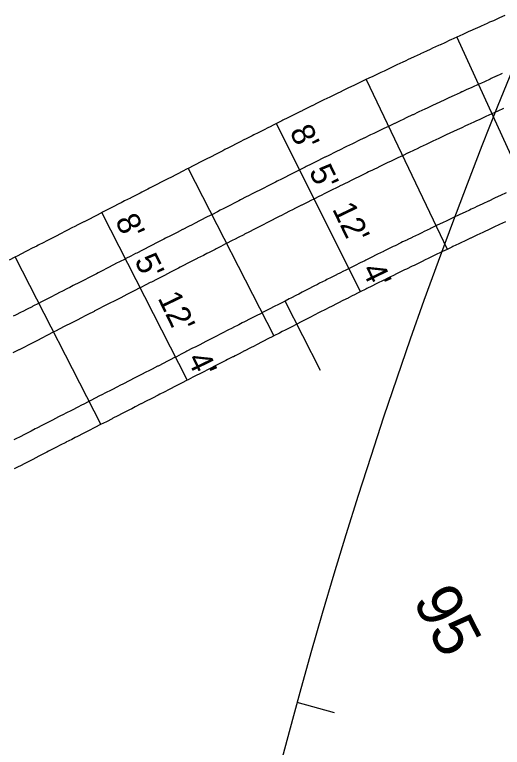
# Model space of a CAD drawing. Extents: x 2145147 to 2158018, y 137519 to 148068.
# Drawn here: x 2150223.5 to 2150298.8, y 143408.6 to 143521.5 of the extents above; entities that cross this region are included whole.
import ezdxf

# ---------------------------------------------------------------- set-up
doc = ezdxf.new("R2010")
doc.units = 0
for name, color, linetype in [('PR_Align_Ramp_A', 7, 'Continuous'), ('PR_Align_Ramp_A_Sta', 7, 'Continuous'), ('PR_Align_Ramp_B', 7, 'Continuous'), ('PR_Dimensions', 7, 'Continuous'), ('PR_Joint_Contraction', 7, 'Continuous'), ('PR_Joint_Long', 7, 'Continuous'), ('PR_Road_Concrete', 7, 'Continuous')]:
    doc.layers.add(name, color=color, linetype=linetype)

msp = doc.modelspace()

# ---------------------------------------------------------------- linework, layer by layer
at = {"layer": 'PR_Align_Ramp_A'}
msp.add_lwpolyline([(2150270.71, 143466.66), (2150265.25, 143477.35)], dxfattribs=at)
at = {"layer": 'PR_Align_Ramp_B'}
msp.add_lwpolyline([(2150272.91, 143413.89), (2150267.13, 143415.47)], dxfattribs=at)
msp.add_arc((2151085.75, 143191.05), 848.83, 152.5051, 261.84091, dxfattribs=at)
at = {"layer": 'PR_Joint_Contraction'}
for p, q in [((2150291.78, 143518.03), (2150303.8, 143491.64)), ((2150277.77, 143511.49), (2150290.27, 143485.32)), ((2150263.88, 143504.69), (2150276.87, 143478.76)), ((2150250.32, 143497.79), (2150263.53, 143471.97)), ((2150236.97, 143490.96), (2150250.18, 143465.14)), ((2150223.61, 143484.13), (2150236.82, 143458.31))]:
    msp.add_line(p, q, dxfattribs=at)
at = {"layer": 'PR_Joint_Long'}
for points in [[(2150298.76, 143512.41), (2150298.56, 143512.32), (2150297.89, 143512.01), (2150297.84, 143511.99), (2150297.06, 143511.64), (2150296.92, 143511.57), (2150296, 143511.16), (2150295.55, 143510.95), (2150295.07, 143510.73), (2150294.16, 143510.32), (2150294.05, 143510.27), (2150293.21, 143509.88), (2150292.58, 143509.6), (2150292.53, 143509.57), (2150292.28, 143509.46), (2150291.35, 143509.03), (2150291, 143508.86), (2150290.43, 143508.61), (2150289.82, 143508.32), (2150289.79, 143508.31), (2150288.58, 143507.74), (2150287.98, 143507.47), (2150287.67, 143507.32), (2150287.27, 143507.13), (2150286.74, 143506.88), (2150286.48, 143506.76), (2150285.8, 143506.44), (2150285.01, 143506.07), (2150284.92, 143506.03), (2150283.96, 143505.57), (2150283.48, 143505.34), (2150283.04, 143505.14), (2150282.18, 143504.73), (2150282.16, 143504.72), (2150281.19, 143504.25), (2150280.49, 143503.92), (2150280.3, 143503.83), (2150279.35, 143503.37), (2150278.96, 143503.18), (2150278.44, 143502.94), (2150277.48, 143502.47), (2150277.42, 143502.44), (2150276.65, 143502.07), (2150276.54, 143502.02), (2150275.97, 143501.74), (2150275.68, 143501.59), (2150274.75, 143501.15), (2150274.45, 143501), (2150273.85, 143500.7), (2150273.07, 143500.32), (2150273.01, 143500.29), (2150272.01, 143499.8), (2150271.45, 143499.52), (2150271.4, 143499.5), (2150271.1, 143499.35), (2150270.19, 143498.9), (2150269.99, 143498.8), (2150269.27, 143498.44), (2150268.5, 143498.06), (2150268.35, 143497.98), (2150267.45, 143497.53), (2150267.01, 143497.31), (2150266.53, 143497.07), (2150266.19, 143496.9), (2150265.6, 143496.61), (2150265.52, 143496.56), (2150264.71, 143496.15), (2150264.04, 143495.81), (2150263.8, 143495.69), (2150262.88, 143495.23), (2150262.54, 143495.06), (2150261.98, 143494.77), (2150260.2, 143493.86), (2150260.2, 143493.86), (2150260.17, 143493.85), (2150259.61, 143493.56), (2150259.28, 143493.39), (2150258.37, 143492.93), (2150258.14, 143492.81), (2150257.51, 143492.48), (2150256.73, 143492.08), (2150256.62, 143492.03), (2150255.72, 143491.57), (2150255.27, 143491.33), (2150254.83, 143491.11), (2150253.94, 143490.66), (2150253.81, 143490.59), (2150253.05, 143490.2), (2150252.36, 143489.85), (2150252.17, 143489.75), (2150251.28, 143489.29), (2150250.91, 143489.1), (2150250.38, 143488.83), (2150249.48, 143488.38), (2150249.44, 143488.35), (2150248.6, 143487.92), (2150248, 143487.62), (2150247.68, 143487.45), (2150247.6, 143487.41), (2150246.82, 143487.02), (2150246.54, 143486.87), (2150245.93, 143486.56), (2150245.12, 143486.14), (2150245.05, 143486.11), (2150244.15, 143485.65), (2150243.66, 143485.4), (2150243.26, 143485.19), (2150242.37, 143484.73), (2150242.2, 143484.65), (2150241.48, 143484.28), (2150240.72, 143483.89), (2150240.57, 143483.81), (2150239.7, 143483.37), (2150239.28, 143483.16), (2150238.81, 143482.91), (2150237.91, 143482.46), (2150237.83, 143482.41), (2150237.02, 143482), (2150236.41, 143481.69), (2150236.15, 143481.56), (2150235.25, 143481.1), (2150234.95, 143480.94), (2150234.36, 143480.64), (2150233.56, 143480.23), (2150233.54, 143480.22), (2150232.57, 143479.72), (2150232.04, 143479.45), (2150231.69, 143479.27), (2150230.81, 143478.82), (2150230.59, 143478.71), (2150229.9, 143478.36), (2150229.12, 143477.96), (2150229.01, 143477.9), (2150228.12, 143477.45), (2150227.67, 143477.22), (2150227.23, 143476.99), (2150226.34, 143476.54), (2150226.22, 143476.47), (2150225.46, 143476.08), (2150224.78, 143475.74), (2150224.56, 143475.62), (2150223.68, 143475.17), (2150223.33, 143475)], [(2150298.98, 143507.02), (2150298.07, 143506.61), (2150297.62, 143506.4), (2150297.14, 143506.18), (2150296.23, 143505.77), (2150296.12, 143505.72), (2150295.29, 143505.34), (2150294.67, 143505.05), (2150294.61, 143505.03), (2150294.37, 143504.92), (2150293.45, 143504.49), (2150293.1, 143504.33), (2150292.53, 143504.07), (2150291.83, 143503.74), (2150291.81, 143503.73), (2150290.69, 143503.21), (2150290.1, 143502.94), (2150289.78, 143502.79), (2150289.39, 143502.6), (2150288.86, 143502.35), (2150288.61, 143502.24), (2150287.93, 143501.92), (2150287.14, 143501.54), (2150287.04, 143501.5), (2150286.1, 143501.06), (2150285.62, 143500.83), (2150285.18, 143500.62), (2150284.28, 143500.19), (2150284.25, 143500.18), (2150283.35, 143499.74), (2150282.64, 143499.41), (2150282.45, 143499.32), (2150281.52, 143498.87), (2150281.13, 143498.68), (2150280.61, 143498.43), (2150279.67, 143497.98), (2150279.61, 143497.95), (2150278.84, 143497.58), (2150278.74, 143497.53), (2150278.15, 143497.24), (2150277.87, 143497.1), (2150276.95, 143496.65), (2150276.65, 143496.51), (2150276.05, 143496.21), (2150275.24, 143495.82), (2150275.19, 143495.79), (2150274.22, 143495.32), (2150273.67, 143495.04), (2150273.63, 143495.02), (2150273.31, 143494.87), (2150272.41, 143494.42), (2150272.21, 143494.32), (2150271.49, 143493.96), (2150270.73, 143493.58), (2150270.58, 143493.51), (2150269.68, 143493.06), (2150269.25, 143492.84), (2150268.77, 143492.6), (2150268.44, 143492.43), (2150267.86, 143492.14), (2150267.77, 143492.1), (2150266.96, 143491.69), (2150266.29, 143491.35), (2150266.06, 143491.23), (2150265.15, 143490.77), (2150264.81, 143490.6), (2150264.25, 143490.31), (2150262.73, 143489.54), (2150262.73, 143489.54), (2150262.45, 143489.4), (2150261.89, 143489.11), (2150261.56, 143488.94), (2150260.66, 143488.48), (2150260.43, 143488.36), (2150259.79, 143488.03), (2150259, 143487.63), (2150258.89, 143487.57), (2150258, 143487.12), (2150257.54, 143486.88), (2150257.11, 143486.66), (2150256.22, 143486.21), (2150256.09, 143486.14), (2150255.33, 143485.75), (2150254.64, 143485.4), (2150254.45, 143485.3), (2150253.55, 143484.84), (2150253.18, 143484.65), (2150252.66, 143484.38), (2150251.76, 143483.93), (2150251.72, 143483.9), (2150250.88, 143483.47), (2150250.28, 143483.17), (2150249.96, 143483.01), (2150249.88, 143482.96), (2150249.1, 143482.56), (2150248.82, 143482.42), (2150248.21, 143482.11), (2150247.39, 143481.69), (2150247.33, 143481.66), (2150246.43, 143481.2), (2150245.93, 143480.94), (2150245.54, 143480.74), (2150244.64, 143480.28), (2150244.47, 143480.2), (2150243.76, 143479.83), (2150243, 143479.44), (2150242.85, 143479.37), (2150241.98, 143478.92), (2150241.56, 143478.71), (2150241.08, 143478.46), (2150240.19, 143478.01), (2150240.11, 143477.96), (2150239.3, 143477.55), (2150238.68, 143477.23), (2150238.43, 143477.1), (2150237.53, 143476.64), (2150237.22, 143476.49), (2150236.63, 143476.19), (2150235.81, 143475.77), (2150235.79, 143475.76), (2150234.85, 143475.27), (2150234.32, 143475), (2150233.97, 143474.82), (2150233.08, 143474.37), (2150232.87, 143474.26), (2150232.18, 143473.91), (2150231.4, 143473.51), (2150231.29, 143473.45), (2150230.4, 143473), (2150229.95, 143472.77), (2150229.51, 143472.54), (2150228.62, 143472.09), (2150228.5, 143472.02), (2150227.73, 143471.63), (2150227.05, 143471.28), (2150226.84, 143471.17), (2150225.96, 143470.72), (2150225.61, 143470.54), (2150225.06, 143470.26), (2150224.22, 143469.83), (2150224.2, 143469.82), (2150223.28, 143469.35)], [(2150299.39, 143494.02), (2150298.48, 143493.6), (2150298.14, 143493.44), (2150297.57, 143493.18), (2150296.67, 143492.76), (2150296.66, 143492.75), (2150295.76, 143492.33), (2150295.18, 143492.06), (2150294.85, 143491.91), (2150294.47, 143491.73), (2150293.95, 143491.49), (2150293.7, 143491.37), (2150293.04, 143491.06), (2150292.23, 143490.68), (2150292.14, 143490.64), (2150291.24, 143490.21), (2150290.75, 143489.98), (2150290.33, 143489.78), (2150289.43, 143489.35), (2150289.29, 143489.28), (2150289.28, 143489.28), (2150288.53, 143488.92), (2150287.81, 143488.58), (2150287.62, 143488.49), (2150286.72, 143488.06), (2150286.34, 143487.87), (2150285.82, 143487.62), (2150284.92, 143487.19), (2150284.87, 143487.16), (2150284.12, 143486.8), (2150284.02, 143486.75), (2150283.4, 143486.45), (2150283.12, 143486.31), (2150282.22, 143485.88), (2150281.94, 143485.73), (2150281.33, 143485.43), (2150280.47, 143485.02), (2150280.43, 143484.99), (2150279.53, 143484.55), (2150279.01, 143484.3), (2150278.97, 143484.27), (2150278.63, 143484.11), (2150277.74, 143483.67), (2150277.55, 143483.57), (2150276.84, 143483.22), (2150276.09, 143482.85), (2150275.95, 143482.77), (2150275.05, 143482.33), (2150274.63, 143482.12), (2150274.16, 143481.88), (2150273.83, 143481.72), (2150273.27, 143481.43), (2150273.17, 143481.38), (2150272.37, 143480.98), (2150271.72, 143480.65), (2150271.48, 143480.53), (2150270.59, 143480.08), (2150270.26, 143479.91), (2150269.7, 143479.62), (2150268.81, 143479.17), (2150268.81, 143479.17), (2150268.72, 143479.12), (2150268.72, 143479.12), (2150267.92, 143478.71), (2150267.36, 143478.43), (2150267.03, 143478.26), (2150266.14, 143477.8), (2150265.91, 143477.68), (2150265.25, 143477.35), (2150264.46, 143476.94), (2150264.36, 143476.89), (2150263.47, 143476.43), (2150263, 143476.2), (2150262.58, 143475.98), (2150261.69, 143475.52), (2150261.55, 143475.45), (2150260.79, 143475.07), (2150260.1, 143474.71), (2150259.9, 143474.61), (2150259.01, 143474.16), (2150258.65, 143473.97), (2150258.12, 143473.7), (2150257.23, 143473.25), (2150257.2, 143473.23), (2150256.34, 143472.79), (2150255.74, 143472.48), (2150255.45, 143472.33), (2150255.37, 143472.29), (2150254.56, 143471.88), (2150254.29, 143471.74), (2150253.67, 143471.42), (2150252.84, 143471), (2150252.78, 143470.97), (2150251.89, 143470.51), (2150251.39, 143470.26), (2150251, 143470.06), (2150250.11, 143469.6), (2150249.94, 143469.51), (2150249.22, 143469.15), (2150248.49, 143468.77), (2150248.33, 143468.69), (2150247.44, 143468.24), (2150247.03, 143468.03), (2150246.55, 143467.78), (2150245.66, 143467.32), (2150245.58, 143467.29), (2150244.77, 143466.87), (2150244.13, 143466.54), (2150243.88, 143466.41), (2150242.99, 143465.96), (2150242.68, 143465.8), (2150242.1, 143465.5), (2150241.23, 143465.06), (2150241.21, 143465.05), (2150240.32, 143464.59), (2150239.78, 143464.31), (2150239.43, 143464.14), (2150238.54, 143463.68), (2150238.32, 143463.57), (2150237.65, 143463.23), (2150236.87, 143462.83), (2150236.76, 143462.77), (2150235.87, 143462.32), (2150235.42, 143462.09), (2150234.98, 143461.86), (2150234.09, 143461.4), (2150233.97, 143461.34), (2150233.2, 143460.95), (2150232.52, 143460.6), (2150232.31, 143460.49), (2150231.42, 143460.04), (2150231.07, 143459.86), (2150230.53, 143459.58), (2150229.64, 143459.13), (2150229.61, 143459.11), (2150228.75, 143458.67), (2150228.16, 143458.37), (2150227.86, 143458.22), (2150226.97, 143457.76), (2150226.71, 143457.63), (2150226.07, 143457.3), (2150225.26, 143456.89), (2150225.19, 143456.85), (2150224.29, 143456.39), (2150223.81, 143456.14), (2150223.4, 143455.94)]]:
    msp.add_lwpolyline(points, dxfattribs=at)
at = {"layer": 'PR_Road_Concrete'}
for points in [[(2150299.18, 143521.35), (2150298.36, 143520.99), (2150298.33, 143520.98), (2150297.39, 143520.56), (2150296.82, 143520.31), (2150296.45, 143520.14), (2150295.51, 143519.71), (2150295.29, 143519.62), (2150294.61, 143519.31), (2150294.57, 143519.29), (2150293.76, 143518.93), (2150293.63, 143518.87), (2150292.69, 143518.44), (2150292.23, 143518.23), (2150291.75, 143518.02), (2150290.81, 143517.59), (2150290.7, 143517.54), (2150289.88, 143517.16), (2150289.23, 143516.86), (2150289.17, 143516.83), (2150288.94, 143516.73), (2150288, 143516.3), (2150287.65, 143516.13), (2150287.07, 143515.86), (2150286.13, 143515.43), (2150286.12, 143515.42), (2150285.2, 143514.99), (2150284.6, 143514.71), (2150284.27, 143514.56), (2150283.87, 143514.38), (2150283.33, 143514.12), (2150283.08, 143514), (2150282.4, 143513.68), (2150281.56, 143513.29), (2150281.47, 143513.24), (2150280.54, 143512.8), (2150280.04, 143512.57), (2150279.6, 143512.36), (2150278.67, 143511.92), (2150278.53, 143511.85), (2150278.52, 143511.85), (2150277.74, 143511.48), (2150277, 143511.12), (2150276.81, 143511.03), (2150275.89, 143510.58), (2150275.49, 143510.39), (2150274.96, 143510.14), (2150274.03, 143509.69), (2150273.98, 143509.66), (2150273.2, 143509.29), (2150273.1, 143509.24), (2150272.46, 143508.93), (2150272.18, 143508.79), (2150271.25, 143508.34), (2150270.95, 143508.19), (2150270.32, 143507.88), (2150269.44, 143507.45), (2150269.4, 143507.43), (2150268.47, 143506.97), (2150267.94, 143506.71), (2150267.9, 143506.69), (2150267.55, 143506.52), (2150266.63, 143506.06), (2150266.43, 143505.96), (2150265.7, 143505.6), (2150264.93, 143505.21), (2150264.78, 143505.14), (2150263.86, 143504.68), (2150263.42, 143504.46), (2150262.94, 143504.22), (2150262.6, 143504.05), (2150262.02, 143503.76), (2150261.92, 143503.71), (2150261.1, 143503.29), (2150260.42, 143502.95), (2150260.18, 143502.83), (2150259.26, 143502.36), (2150258.92, 143502.19), (2150258.34, 143501.89), (2150257.43, 143501.43), (2150257.42, 143501.42), (2150257.33, 143501.38), (2150257.33, 143501.38), (2150256.53, 143500.97), (2150255.97, 143500.68), (2150255.64, 143500.51), (2150254.75, 143500.06), (2150254.52, 143499.94), (2150253.86, 143499.6), (2150253.07, 143499.2), (2150252.97, 143499.15), (2150252.08, 143498.69), (2150251.62, 143498.45), (2150251.19, 143498.23), (2150250.3, 143497.78), (2150250.17, 143497.71), (2150249.41, 143497.32), (2150248.71, 143496.97), (2150248.52, 143496.87), (2150247.63, 143496.41), (2150247.26, 143496.23), (2150246.74, 143495.96), (2150245.85, 143495.5), (2150245.81, 143495.48), (2150244.96, 143495.05), (2150244.36, 143494.74), (2150244.07, 143494.59), (2150243.98, 143494.55), (2150243.18, 143494.14), (2150242.91, 143494), (2150242.29, 143493.68), (2150241.46, 143493.26), (2150241.4, 143493.22), (2150240.51, 143492.77), (2150240, 143492.51), (2150239.62, 143492.31), (2150238.73, 143491.86), (2150238.55, 143491.77), (2150237.83, 143491.4), (2150237.1, 143491.03), (2150236.94, 143490.95), (2150236.05, 143490.49), (2150235.65, 143490.28), (2150235.17, 143490.04), (2150234.27, 143489.58), (2150234.2, 143489.54), (2150233.38, 143489.13), (2150232.74, 143488.8), (2150232.49, 143488.67), (2150231.6, 143488.21), (2150231.29, 143488.06), (2150230.71, 143487.76), (2150229.84, 143487.31), (2150229.82, 143487.3), (2150228.93, 143486.85), (2150228.39, 143486.57), (2150228.04, 143486.39), (2150227.15, 143485.94), (2150226.94, 143485.83), (2150226.26, 143485.48), (2150225.49, 143485.08), (2150225.37, 143485.03), (2150224.48, 143484.57), (2150224.03, 143484.34), (2150223.59, 143484.12), (2150222.7, 143483.66)], [(2150299.26, 143489.55), (2150298.35, 143489.13), (2150298.34, 143489.12), (2150297.45, 143488.71), (2150296.87, 143488.44), (2150296.55, 143488.29), (2150296.17, 143488.11), (2150295.65, 143487.87), (2150295.4, 143487.75), (2150294.75, 143487.44), (2150293.93, 143487.06), (2150293.85, 143487.02), (2150292.95, 143486.59), (2150292.47, 143486.37), (2150292.05, 143486.17), (2150291.15, 143485.74), (2150291.01, 143485.67), (2150291, 143485.67), (2150290.25, 143485.31), (2150289.54, 143484.97), (2150289.35, 143484.88), (2150288.46, 143484.45), (2150288.07, 143484.27), (2150287.56, 143484.02), (2150286.67, 143483.59), (2150286.61, 143483.56), (2150285.87, 143483.2), (2150285.77, 143483.15), (2150285.15, 143482.85), (2150284.87, 143482.72), (2150283.98, 143482.28), (2150283.69, 143482.14), (2150283.09, 143481.84), (2150282.24, 143481.43), (2150282.19, 143481.4), (2150281.3, 143480.96), (2150280.78, 143480.71), (2150280.74, 143480.69), (2150280.41, 143480.52), (2150279.52, 143480.08), (2150279.33, 143479.99), (2150278.62, 143479.64), (2150277.87, 143479.27), (2150277.73, 143479.2), (2150276.84, 143478.75), (2150276.42, 143478.54), (2150275.96, 143478.3), (2150275.63, 143478.14), (2150275.07, 143477.86), (2150274.97, 143477.81), (2150274.18, 143477.41), (2150273.52, 143477.08), (2150273.29, 143476.96), (2150272.4, 143476.51), (2150272.08, 143476.35), (2150271.51, 143476.06), (2150270.63, 143475.61), (2150270.63, 143475.61), (2150270.54, 143475.56), (2150270.54, 143475.56), (2150269.74, 143475.15), (2150269.18, 143474.86), (2150268.85, 143474.69), (2150267.96, 143474.24), (2150267.73, 143474.12), (2150267.07, 143473.78), (2150266.28, 143473.38), (2150266.18, 143473.33), (2150265.29, 143472.87), (2150264.83, 143472.64), (2150264.4, 143472.42), (2150263.51, 143471.96), (2150263.37, 143471.89), (2150262.62, 143471.51), (2150261.92, 143471.15), (2150261.73, 143471.05), (2150260.84, 143470.6), (2150260.47, 143470.41), (2150259.95, 143470.14), (2150259.06, 143469.68), (2150259.02, 143469.67), (2150258.17, 143469.23), (2150257.57, 143468.92), (2150257.28, 143468.77), (2150257.19, 143468.73), (2150256.38, 143468.32), (2150256.12, 143468.18), (2150255.49, 143467.86), (2150254.66, 143467.44), (2150254.6, 143467.41), (2150253.71, 143466.95), (2150253.21, 143466.69), (2150252.82, 143466.5), (2150251.93, 143466.04), (2150251.76, 143465.95), (2150251.04, 143465.59), (2150250.31, 143465.21), (2150250.15, 143465.13), (2150249.26, 143464.67), (2150248.86, 143464.47), (2150248.37, 143464.22), (2150247.48, 143463.76), (2150247.4, 143463.72), (2150246.59, 143463.31), (2150245.95, 143462.98), (2150245.7, 143462.85), (2150244.81, 143462.4), (2150244.5, 143462.24), (2150243.92, 143461.94), (2150243.05, 143461.5), (2150243.03, 143461.49), (2150242.14, 143461.03), (2150241.6, 143460.75), (2150241.25, 143460.58), (2150240.36, 143460.12), (2150240.15, 143460.01), (2150239.47, 143459.66), (2150238.69, 143459.27), (2150238.58, 143459.21), (2150237.69, 143458.75), (2150237.24, 143458.52), (2150236.8, 143458.3), (2150235.91, 143457.84), (2150235.79, 143457.78), (2150235.02, 143457.39), (2150234.34, 143457.04), (2150234.13, 143456.93), (2150233.24, 143456.48), (2150232.89, 143456.3), (2150232.35, 143456.02), (2150231.46, 143455.57), (2150231.44, 143455.55), (2150230.57, 143455.11), (2150229.98, 143454.81), (2150229.68, 143454.65), (2150228.79, 143454.2), (2150228.53, 143454.07), (2150227.9, 143453.74), (2150227.08, 143453.33), (2150227.01, 143453.29), (2150226.12, 143452.83), (2150225.63, 143452.58), (2150225.23, 143452.38), (2150224.34, 143451.92), (2150224.18, 143451.84), (2150223.45, 143451.47)]]:
    msp.add_lwpolyline(points, dxfattribs=at)

# ---------------------------------------------------------------- texts
at = {"layer": 'PR_Align_Ramp_A_Sta'}
msp.add_text('95', height=7, rotation=297.0949, dxfattribs=at).set_placement((2150284.9, 143431.24))
at = {"layer": 'PR_Dimensions'}
for s, p in [("8'", (2150265.9, 143503.48)), ("5'", (2150268.88, 143497.35)), ("12'", (2150272.48, 143491.55)), ("8'", (2150238.98, 143489.75)), ("5'", (2150241.96, 143483.62)), ("4'", (2150277.01, 143482.2)), ("12'", (2150245.56, 143477.81)), ("4'", (2150250.09, 143468.46))]:
    msp.add_text(s, height=3.6, rotation=295.8325, dxfattribs=at).set_placement(p)

doc.saveas('drawing.dxf')
